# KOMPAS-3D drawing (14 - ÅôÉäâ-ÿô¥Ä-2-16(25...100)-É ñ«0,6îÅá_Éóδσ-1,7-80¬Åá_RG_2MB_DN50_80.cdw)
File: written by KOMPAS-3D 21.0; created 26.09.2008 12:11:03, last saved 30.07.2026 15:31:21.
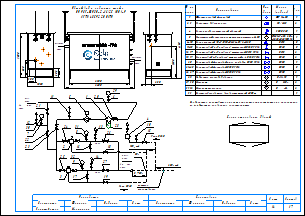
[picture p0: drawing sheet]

Sheets 1-2: A3, landscape

Document properties: Наименование: Макро:21; Автор: RaskoAdmin; Форматы листов документа: 2xA3; Полное имя файла: \\ur38nt01\Departments\КТО\КБ ПУРДГ\Заявки\Прайс-лист на типовые шкафы ГРПШ\ПУРДГ_стандарт_30_04_2026\ПУРДГ с RG_2MB\ПУРДГ-ШУЭО-2-16(25...100)-Р до0,6МПа_Рвых-1,7-80кПа_RG_2MB_DN50_80.cdw

Title block, sheet 1: Наименование: Пункт учета газа / ПУГ-Ш-400-Р / ЛГТИ.485922.001ТУ; designation: ЛГТИ.03.4411141; sheet number: 1; Количество листов документа: 2; organisation: ООО "ЭЛЬСТЕР Газэлектроника"; Форматы листов документа: A3; stored path: C:\Рабочие документы\Компас\ПУГ\Схема.cdw; Разработал: Устинов; Проверил: Кошкин; Утвердил: Кошкин
Title block, sheet 2: sheet number: 2; stored path: D:\Рабочие документы\Заявки\ПУРДГ\ПУРДГ-ШУЭО-2-100-Р 4411220.cdw; designation, second copy: ЛГТИ.03.4411141-

Views: Вид 1, Вид 2
Referenced files: wcvoit.frw
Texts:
  Normal
  № на
  схеме
  Усл.
  обозн.
  Марка
  (модель)
  Кол.
  Фильтр газовый фланцевый
  ФГ 16-50
  Регулятор давления газа
  RG/2MB
  Клапан предохранительный сбросной
  КПС DN20
  Измерительный комплекс с ротационным счетчиком Ду50
  СГ-ЭК-Р-(0,2...2,0)-
  Кран кнопочный VE-РАСКО-НЗ-1,6-G1/2-М20
  DN15
  Кран шаровой "под приварку" штуцерный DN20 PN16
  DN20
  Кран шаровой "под приварку" штуцерный DN15 PN16
  Кран шаровой "под приварку" штуцерный п/п DN20 PN16
  Кран шаровой фланцевый с мех. приводом DN50 PN16
  Кран шаровой фланцевый DN50 PN16
  Кран шаровой фланцевый DN80 PN16
  DN50
  DN80
  Индикатор перепада давления
  Манометр
  Манометр-напоромер
  Электрообогреватель взрывозащищенный 400Вт
  Delta 15
  0...     МПа
  0...     кПа
  Общий вид и габариты шкафа
  ПУРДГ-ШУЭО-2-16(25...100)-Р
  Выход газа
  Вход газа
  logo-rasko-ge.png
  DN 1
  местное
  сопротивление
  Римп DN20
  Выход
  газа
  Р=     кПа
  Вход
  Р=       МПа
  PDI
  Схема открывания дверей
  Предприятие изготовитель может заменять комплектующие на аналогичные,
  не ухудшающие заявленных характеристик.
  Должность
  Конструктор
  Фамилия
  Подпись
  Дата
  Согласовано
  Максимкин
  Лист
  Листов
  POLYLINE_STYLE_0.18_RGB_0_0_0
  POLYLINE_STYLE_0.50_RGB_0_0_0
  POLYLINE_STYLE_0.34_RGB_0_0_0
  PHANTOM_RGB_0_0_0_SC_1_THICK_0.18
  K5LT_THIN_RGB_0_0_0_THICK_0.18
  K5LT32769_RGB_0_0_0_THICK_0.18
  K5LT12_RGB_0_0_0_SC_1_THICK_0.18
  K5LT_DASHED_RGB_0_0_0_SC_1_THICK_0.18
  ACISOTGL_RGB_0_0_0_SC_0.8_THICK_0.25
  CONTINUOUS_RGB_0_127_31_THICK_0.3
  CONTINUOUS_RGB_0_0_255_THICK_0.35
  CONTINUOUS_RGB_255_0_0_THICK_0.35
  POLYLINE_STYLE_0.25_RGB_0_0_0
  CONTINUOUS_RGB_0_0_0_THICK_0.5
  POLYLINE_STYLE_0.35_RGB_0_0_255
  CONTINUOUS_RGB_0_0_0_THICK_0.4
  CONTINUOUS_RGB_0_0_0_THICK_0.35
  НЕВИДИМАЯ_RGB_0_0_0_SC_0.3_THICK_0.25
  СONTINUOUS_RGB_0_0_0_THICK_0.25
  ОСЕВАЯ2_RGB_248_153_30_SC_0.3_THICK_0.25
  Без оформления
Dimensions and other numbers on the sheet: 1; 2, 3; 2; 4; 5; 6-10; 11-15; 16, 17; 18, 19; 20; 21-25; 26, 27; 28; 29, 30; 31, 32; 33; 1500; 250; 300; 1050; 550; 305; 2300; 4130; 2000; 2600; 5,,,7DN 1; 7; 30; 12; 21; 22; 23; 11; 6; 29; 24; 31; 8; 16; 13; 26; 18; 10; 15; 25; 32; 9; 3; 17; 14; 27; 19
